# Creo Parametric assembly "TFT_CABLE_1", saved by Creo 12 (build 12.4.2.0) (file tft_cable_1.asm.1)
Units: Custom; MM, KILOGRAM, SECS

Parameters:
  PTC_WM_ITERATION = "0"
  PTC_WM_VERSION = "-.0"
  PTC_WM_LIFECYCLE_STATE = "In Work"
  PTC_WM_LIFECYCLE = "MO_CADDocument"
  PTC_WM_CREATED_BY = "Maximilian Roepper (Z0017RMS: MO)"
  PTC_WM_CREATED_ON = "18-Sep-26 11:36:42 AM"
  PTC_WM_MODIFIED_BY = "Maximilian Roepper (Z0017RMS: MO)"
  PTC_WM_MODIFIED_ON = "18-Sep-26 11:36:46 AM"
  PDMLINKNUMBER = "PDM000071455253"
  PTC_WM_NAME = "tft_cable_1.asm"
  PTC_WM_NUMBER = "PDM000071455253"

Other parameters: WEIGHT, WEIGHT_FACTOR, WEIGHT_ADD, MC_ERRORS, SUPPLIER, ISPOSITIONINGASSEMBLY

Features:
  1. coordinate system
  2. imported feature
  3. component "LIGHT_SHELF_1"
  4. component "MAIN_SHELF_1"

Other named items: DRW_VIEW_ORG, ROUGH-GROB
